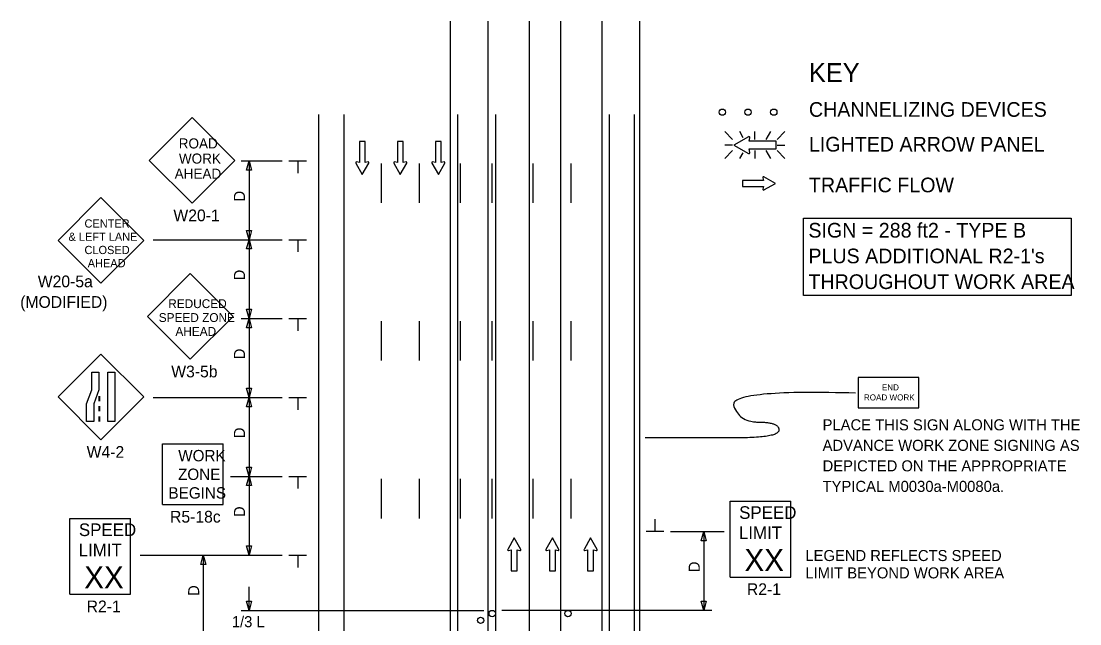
# Model space of a CAD drawing. Extents: x 16730 to 19504, y 5662 to 6979.
# Drawn here: x 16730 to 17400, y 6547 to 6929 of the extents above; entities that cross this region are included whole.
import ezdxf

# ---------------------------------------------------------------- set-up
doc = ezdxf.new("R2010")
doc.units = 0
for name, color, linetype in [('ALI_LEGAL_EX', 7, 'Continuous'), ('MT_SCRATCH_LEVEL_E', 7, 'Continuous'), ('PAVT_EDGE_EX', 7, 'Continuous'), ('TRAFFIC_SIGNS_PR', 7, 'Continuous'), ('TYPICAL_TEXT_DIMEN_EX', 7, 'Continuous'), ('TYPICAL_TEXT_DIMEN_PR', 7, 'Continuous')]:
    doc.layers.add(name, color=color, linetype=linetype)

msp = doc.modelspace()

# ---------------------------------------------------------------- linework, layer by layer
at = {"layer": 'ALI_LEGAL_EX'}
for p, q in [((17001.36, 6131.68), (17001.36, 6928.96)), ((17001.36, 6131.68), (17001.36, 6928.96)), ((17025.36, 6131.68), (17025.36, 6928.96)), ((17025.36, 6131.68), (17025.36, 6928.96)), ((17051.36, 6131.68), (17051.36, 6928.96)), ((17051.36, 6131.68), (17051.36, 6928.96)), ((17071.36, 6131.68), (17071.36, 6928.96)), ((17071.36, 6131.68), (17071.36, 6928.96)), ((17097.36, 6131.68), (17097.36, 6928.96)), ((17097.36, 6131.68), (17097.36, 6928.96)), ((17121.36, 6131.68), (17121.36, 6928.96)), ((17121.36, 6131.68), (17121.36, 6928.96))]:
    msp.add_line(p, q, dxfattribs=at)
for points in [[(16957.81, 6813.81), (16957.81, 6838.81)], [(16981.81, 6813.81), (16981.81, 6838.81)], [(17007.81, 6813.81), (17007.81, 6838.81)], [(17027.81, 6813.81), (17027.81, 6838.81)], [(17053.81, 6813.81), (17053.81, 6838.81)], [(17077.81, 6813.81), (17077.81, 6838.81)], [(16957.81, 6713.81), (16957.81, 6738.81)], [(16981.81, 6713.81), (16981.81, 6738.81)], [(17007.81, 6713.81), (17007.81, 6738.81)], [(17027.81, 6713.81), (17027.81, 6738.81)], [(17053.81, 6713.81), (17053.81, 6738.81)], [(17077.81, 6713.81), (17077.81, 6738.81)], [(16957.81, 6613.81), (16957.81, 6638.81)], [(16981.81, 6613.81), (16981.81, 6638.81)], [(17007.81, 6613.81), (17007.81, 6638.81)], [(17027.81, 6613.81), (17027.81, 6638.81)], [(17053.81, 6613.81), (17053.81, 6638.81)], [(17077.81, 6613.81), (17077.81, 6638.81)]]:
    msp.add_lwpolyline(points, dxfattribs=at)
at = {"layer": 'MT_SCRATCH_LEVEL_E'}
for p, q in [((16947.41, 6852.65), (16943.67, 6852.65)), ((16943.67, 6852.65), (16943.67, 6839.4)), ((16947.41, 6852.65), (16943.67, 6852.65)), ((16943.67, 6852.65), (16943.67, 6839.4)), ((16947.41, 6839.4), (16947.41, 6852.65)), ((16947.41, 6839.4), (16947.41, 6852.65)), ((16971.48, 6852.65), (16967.74, 6852.65)), ((16967.74, 6852.65), (16967.74, 6839.4)), ((16971.48, 6852.65), (16967.74, 6852.65)), ((16967.74, 6852.65), (16967.74, 6839.4)), ((16971.48, 6839.4), (16971.48, 6852.65)), ((16971.48, 6839.4), (16971.48, 6852.65)), ((16995.55, 6852.65), (16991.81, 6852.65)), ((16991.81, 6852.65), (16991.81, 6839.4)), ((16995.55, 6852.65), (16991.81, 6852.65)), ((16991.81, 6852.65), (16991.81, 6839.4)), ((16995.55, 6839.4), (16995.55, 6852.65)), ((16995.55, 6839.4), (16995.55, 6852.65)), ((16941.41, 6839.03), (16945.56, 6831.79)), ((16941.41, 6839.03), (16945.56, 6831.79)), ((16943.67, 6839.4), (16941.89, 6839.71)), ((16943.67, 6839.4), (16941.89, 6839.71)), ((16945.56, 6831.79), (16949.67, 6839.03)), ((16945.56, 6831.79), (16949.67, 6839.03)), ((16949.19, 6839.71), (16947.41, 6839.4)), ((16949.19, 6839.71), (16947.41, 6839.4)), ((16965.48, 6839.03), (16969.63, 6831.79)), ((16965.48, 6839.03), (16969.63, 6831.79)), ((16967.74, 6839.4), (16965.96, 6839.71)), ((16967.74, 6839.4), (16965.96, 6839.71)), ((16969.63, 6831.79), (16973.74, 6839.03)), ((16969.63, 6831.79), (16973.74, 6839.03)), ((16973.26, 6839.71), (16971.48, 6839.4)), ((16973.26, 6839.71), (16971.48, 6839.4)), ((16989.55, 6839.03), (16993.7, 6831.79)), ((16989.55, 6839.03), (16993.7, 6831.79)), ((16991.81, 6839.4), (16990.03, 6839.71)), ((16991.81, 6839.4), (16990.03, 6839.71)), ((16993.7, 6831.79), (16997.81, 6839.03)), ((16993.7, 6831.79), (16997.81, 6839.03)), ((16997.33, 6839.71), (16995.55, 6839.4)), ((16997.33, 6839.71), (16995.55, 6839.4)), ((17199.58, 6827.97), (17186.32, 6827.97)), ((17186.32, 6827.97), (17186.32, 6824.23)), ((17199.58, 6827.97), (17186.32, 6827.97)), ((17186.32, 6827.97), (17186.32, 6824.23)), ((17199.26, 6829.75), (17199.58, 6827.97)), ((17199.26, 6829.75), (17199.58, 6827.97)), ((17207.19, 6826.12), (17199.94, 6830.23)), ((17207.19, 6826.12), (17199.94, 6830.23)), ((17199.94, 6821.98), (17207.19, 6826.12)), ((17199.94, 6821.98), (17207.19, 6826.12)), ((17186.32, 6824.23), (17199.58, 6824.23)), ((17186.32, 6824.23), (17199.58, 6824.23)), ((17199.58, 6824.23), (17199.26, 6822.45)), ((17199.58, 6824.23), (17199.26, 6822.45)), ((17041.75, 6601.44), (17037.64, 6594.2)), ((17041.75, 6601.44), (17037.64, 6594.2)), ((17045.89, 6594.2), (17041.75, 6601.44)), ((17045.89, 6594.2), (17041.75, 6601.44)), ((17065.92, 6601.44), (17061.81, 6594.2)), ((17065.92, 6601.44), (17061.81, 6594.2)), ((17070.06, 6594.2), (17065.92, 6601.44)), ((17070.06, 6594.2), (17065.92, 6601.44)), ((17090.09, 6601.44), (17085.97, 6594.2)), ((17090.09, 6601.44), (17085.97, 6594.2)), ((17094.23, 6594.2), (17090.09, 6601.44)), ((17094.23, 6594.2), (17090.09, 6601.44)), ((17038.12, 6593.52), (17039.89, 6593.83)), ((17038.12, 6593.52), (17039.89, 6593.83)), ((17039.89, 6593.83), (17039.89, 6580.58)), ((17039.89, 6593.83), (17039.89, 6580.58)), ((17043.64, 6580.58), (17043.64, 6593.83)), ((17043.64, 6593.83), (17045.41, 6593.52)), ((17043.64, 6580.58), (17043.64, 6593.83)), ((17043.64, 6593.83), (17045.41, 6593.52)), ((17062.29, 6593.52), (17064.06, 6593.83)), ((17062.29, 6593.52), (17064.06, 6593.83)), ((17064.06, 6593.83), (17064.06, 6580.58)), ((17064.06, 6593.83), (17064.06, 6580.58)), ((17067.81, 6580.58), (17067.81, 6593.83)), ((17067.81, 6593.83), (17069.58, 6593.52)), ((17067.81, 6580.58), (17067.81, 6593.83)), ((17067.81, 6593.83), (17069.58, 6593.52)), ((17086.46, 6593.52), (17088.23, 6593.83)), ((17086.46, 6593.52), (17088.23, 6593.83)), ((17088.23, 6593.83), (17088.23, 6580.58)), ((17088.23, 6593.83), (17088.23, 6580.58)), ((17091.98, 6580.58), (17091.98, 6593.83)), ((17091.98, 6593.83), (17093.75, 6593.52)), ((17091.98, 6580.58), (17091.98, 6593.83)), ((17091.98, 6593.83), (17093.75, 6593.52)), ((17039.89, 6580.58), (17043.64, 6580.58)), ((17039.89, 6580.58), (17043.64, 6580.58)), ((17064.06, 6580.58), (17067.81, 6580.58)), ((17064.06, 6580.58), (17067.81, 6580.58)), ((17088.23, 6580.58), (17091.98, 6580.58)), ((17088.23, 6580.58), (17091.98, 6580.58))]:
    msp.add_line(p, q, dxfattribs=at)
for centre, start, end in [((16941.82, 6839.25), 80.03619, 209.77312), ((16941.82, 6839.25), 80.03619, 209.77312), ((16949.26, 6839.25), 330.42484, 99.96381), ((16949.26, 6839.25), 330.42484, 99.96381), ((16965.89, 6839.25), 80.03619, 209.77312), ((16965.89, 6839.25), 80.03619, 209.77312), ((16973.33, 6839.25), 330.42484, 99.96381), ((16973.33, 6839.25), 330.42484, 99.96381), ((16989.96, 6839.25), 80.03619, 209.77312), ((16989.96, 6839.25), 80.03619, 209.77312), ((16997.4, 6839.25), 330.42484, 99.96381), ((16997.4, 6839.25), 330.42484, 99.96381), ((17199.72, 6829.82), 60.42484, 189.96381), ((17199.72, 6829.82), 60.42484, 189.96381), ((17199.72, 6822.38), 170.03619, 299.77312), ((17199.72, 6822.38), 170.03619, 299.77312), ((17038.04, 6593.98), 150.42484, 279.96381), ((17038.04, 6593.98), 150.42484, 279.96381), ((17045.48, 6593.98), 260.03619, 29.77312), ((17045.48, 6593.98), 260.03619, 29.77312), ((17062.21, 6593.98), 150.42484, 279.96381), ((17062.21, 6593.98), 150.42484, 279.96381), ((17069.65, 6593.98), 260.03619, 29.77312), ((17069.65, 6593.98), 260.03619, 29.77312), ((17086.38, 6593.98), 150.42484, 279.96381), ((17086.38, 6593.98), 150.42484, 279.96381), ((17093.82, 6593.98), 260.03619, 29.77312), ((17093.82, 6593.98), 260.03619, 29.77312)]:
    msp.add_arc(centre, 0.463, start, end, dxfattribs=at)
at = {"layer": 'PAVT_EDGE_EX'}
for p, q in [((16917.81, 6869.88), (16917.81, 6101.02)), ((16933.81, 6869.88), (16933.81, 6101.02)), ((17005.81, 6869.88), (17005.81, 6101.02)), ((17029.81, 6869.88), (17029.81, 6101.02)), ((17101.81, 6869.88), (17101.81, 6101.02)), ((17117.81, 6869.88), (17117.81, 6101.02))]:
    msp.add_line(p, q, dxfattribs=at)
at = {"layer": 'TRAFFIC_SIGNS_PR'}
for p, q in [((16837.75, 6867.89), (16810.59, 6840.74)), ((16864.9, 6840.74), (16837.75, 6867.89)), ((17175.05, 6858.93), (17179.98, 6853.99)), ((17186.81, 6855.11), (17184.6, 6858.93)), ((17194.13, 6853.99), (17194.13, 6858.93)), ((17201.37, 6853.99), (17204.22, 6858.93)), ((17208.28, 6853.99), (17213.22, 6858.93)), ((17179.98, 6850.44), (17175.05, 6850.44)), ((17175.05, 6841.95), (17179.98, 6846.88)), ((17184.56, 6841.95), (17186.67, 6845.61)), ((17194.13, 6846.88), (17194.13, 6841.95)), ((17204.26, 6841.95), (17201.41, 6846.88)), ((17208.28, 6850.44), (17213.22, 6850.44)), ((17208.28, 6846.88), (17213.22, 6841.95)), ((16810.59, 6840.74), (16837.75, 6813.59)), ((16837.75, 6813.59), (16864.9, 6840.74)), ((16780.03, 6817.18), (16752.88, 6790.03)), ((16807.18, 6790.03), (16780.03, 6817.18)), ((16752.88, 6790.03), (16780.03, 6762.88)), ((16780.03, 6762.88), (16807.18, 6790.03)), ((16836.59, 6768.95), (16809.44, 6741.8)), ((16863.75, 6741.8), (16836.59, 6768.95)), ((16809.44, 6741.8), (16836.59, 6714.65)), ((16836.59, 6714.65), (16863.75, 6741.8)), ((16780.03, 6717.95), (16752.88, 6690.8)), ((16780.03, 6717.95), (16752.88, 6690.8)), ((16807.19, 6690.8), (16780.03, 6717.95)), ((16807.18, 6690.8), (16780.03, 6717.95)), ((16778.78, 6691.29), (16778.78, 6688.09)), ((16779.18, 6691.29), (16779.18, 6688.09)), ((16752.88, 6690.8), (16780.03, 6663.65)), ((16752.88, 6690.8), (16780.03, 6663.65)), ((16778.78, 6684.89), (16778.78, 6681.69)), ((16779.18, 6684.89), (16779.18, 6681.69)), ((16780.03, 6663.65), (16807.19, 6690.8)), ((16780.03, 6663.65), (16807.18, 6690.8)), ((16778.78, 6678.49), (16778.78, 6675.29)), ((16779.18, 6678.49), (16779.18, 6675.29)), ((16818.98, 6622.61), (16818.98, 6661.01)), ((16818.98, 6661.01), (16857.38, 6661.01)), ((16857.38, 6622.61), (16857.38, 6661.01)), ((17178.45, 6624.66), (17216.85, 6624.66)), ((17178.45, 6576.66), (17178.45, 6624.66)), ((17216.85, 6576.66), (17216.85, 6624.66)), ((16818.98, 6622.61), (16857.38, 6622.61)), ((16760.3, 6613.76), (16798.7, 6613.76)), ((16760.3, 6565.76), (16760.3, 6613.76)), ((16798.7, 6565.76), (16798.7, 6613.76)), ((17178.45, 6576.66), (17216.85, 6576.66)), ((16760.3, 6565.76), (16798.7, 6565.76))]:
    msp.add_line(p, q, dxfattribs=at)
for points in [[(17190.06, 6855.72), (17180.77, 6850.44), (17190.06, 6845.12)], [(17190.94, 6845.75), (17190.53, 6848.01), (17207.55, 6848.01), (17207.55, 6852.82), (17190.53, 6852.82), (17190.94, 6855.1)]]:
    msp.add_lwpolyline(points, dxfattribs=at)
for points in [[(16778.78, 6706.54), (16778.78, 6695.36), (16775.44, 6686.47), (16775.44, 6675.29), (16770.95, 6675.29), (16770.95, 6686.47), (16774.29, 6695.36), (16774.29, 6706.54)], [(16778.78, 6706.54), (16778.78, 6695.36), (16775.44, 6686.47), (16775.44, 6675.29), (16770.95, 6675.29), (16770.95, 6686.47), (16774.29, 6695.36), (16774.29, 6706.54)], [(16788.92, 6706.54), (16788.92, 6675.29), (16784.43, 6675.29), (16784.43, 6706.54)], [(16788.92, 6706.54), (16788.92, 6675.29), (16784.43, 6675.29), (16784.43, 6706.54)], [(17259.6, 6683.82), (17298, 6683.82), (17298, 6703.02), (17259.6, 6703.02)]]:
    msp.add_lwpolyline(points, close=True, dxfattribs=at)
for centre in [(17173.56, 6871.28), (17189.86, 6871.28), (17206.16, 6871.28), (17020.5, 6549.17), (17027.8, 6553.52), (17075.79, 6553.52), (17075.79, 6553.52)]:
    msp.add_circle(centre, 2, dxfattribs=at)
for centre, radius, start, end in [((17190.35, 6855.19), 0.598, 350.73078, 118.89165), ((17190.35, 6845.64), 0.597, 241.48329, 9.95933)]:
    msp.add_arc(centre, radius, start, end, dxfattribs=at)
at = {"layer": 'TYPICAL_TEXT_DIMEN_EX'}
msp.add_lwpolyline([(17225.06, 6804.2), (17394.51, 6804.2), (17394.51, 6755.01), (17225.06, 6755.01)], close=True, dxfattribs=at)
at = {"layer": 'TYPICAL_TEXT_DIMEN_PR'}
for p, q in [((16868.81, 6840.47), (16894.81, 6840.47)), ((16872.24, 6834.6), (16873.81, 6840.47)), ((16873.81, 6840.47), (16875.38, 6834.6)), ((16873.81, 6840.47), (16873.81, 6790.47)), ((16899.06, 6840.47), (16910.31, 6840.47)), ((16904.69, 6840.47), (16904.69, 6832.68)), ((16873.81, 6834.6), (16872.24, 6834.6)), ((16875.38, 6834.6), (16873.81, 6834.6)), ((16873.81, 6790.47), (16872.24, 6796.33)), ((16872.24, 6796.33), (16873.81, 6796.33)), ((16873.81, 6796.33), (16875.38, 6796.33)), ((16875.38, 6796.33), (16873.81, 6790.47)), ((16813.08, 6790.47), (16894.81, 6790.47)), ((16868.81, 6790.47), (16894.81, 6790.47)), ((16872.24, 6784.6), (16873.81, 6790.47)), ((16873.81, 6790.47), (16873.81, 6740.47)), ((16873.81, 6790.47), (16875.38, 6784.6)), ((16899.06, 6790.47), (16910.31, 6790.47)), ((16904.69, 6790.47), (16904.69, 6782.68)), ((16873.81, 6784.6), (16872.24, 6784.6)), ((16875.38, 6784.6), (16873.81, 6784.6)), ((16873.81, 6740.47), (16872.24, 6746.33)), ((16872.24, 6746.33), (16873.81, 6746.33)), ((16873.81, 6746.33), (16875.38, 6746.33)), ((16875.38, 6746.33), (16873.81, 6740.47)), ((16868.81, 6740.47), (16894.81, 6740.47)), ((16872.24, 6734.6), (16873.81, 6740.47)), ((16873.81, 6740.47), (16873.81, 6690.47)), ((16873.81, 6740.47), (16875.38, 6734.6)), ((16899.06, 6740.47), (16910.31, 6740.47)), ((16904.69, 6740.47), (16904.69, 6732.68)), ((16873.81, 6734.6), (16872.24, 6734.6)), ((16875.38, 6734.6), (16873.81, 6734.6)), ((16873.81, 6690.47), (16872.24, 6696.33)), ((16872.24, 6696.33), (16873.81, 6696.33)), ((16873.81, 6696.33), (16875.38, 6696.33)), ((16875.38, 6696.33), (16873.81, 6690.47)), ((16813.08, 6690.47), (16894.81, 6690.47)), ((16868.81, 6690.47), (16894.81, 6690.47)), ((16872.24, 6684.6), (16873.81, 6690.47)), ((16873.81, 6684.6), (16872.24, 6684.6)), ((16873.81, 6690.47), (16875.38, 6684.6)), ((16873.81, 6690.47), (16873.81, 6640.47)), ((16875.38, 6684.6), (16873.81, 6684.6)), ((16899.06, 6690.47), (16910.31, 6690.47)), ((16904.69, 6690.47), (16904.69, 6682.68)), ((16873.81, 6640.47), (16872.24, 6646.33)), ((16872.24, 6646.33), (16873.81, 6646.33)), ((16873.81, 6646.33), (16875.38, 6646.33)), ((16875.38, 6646.33), (16873.81, 6640.47)), ((16862.15, 6640.47), (16894.81, 6640.47)), ((16872.24, 6634.6), (16873.81, 6640.47)), ((16873.81, 6640.47), (16873.81, 6590.47)), ((16873.81, 6640.47), (16875.38, 6634.6)), ((16899.06, 6640.47), (16910.31, 6640.47)), ((16904.69, 6640.47), (16904.69, 6632.68)), ((16873.81, 6634.6), (16872.24, 6634.6)), ((16875.38, 6634.6), (16873.81, 6634.6)), ((17130.94, 6605.53), (17130.94, 6613.32)), ((17136.56, 6605.53), (17125.31, 6605.53)), ((17140.81, 6605.53), (17174.82, 6605.53)), ((17160.24, 6599.67), (17161.81, 6605.53)), ((17161.81, 6605.53), (17161.81, 6555.53)), ((17161.81, 6605.53), (17163.38, 6599.67)), ((17161.81, 6599.67), (17160.24, 6599.67)), ((17163.38, 6599.67), (17161.81, 6599.67)), ((16873.81, 6590.47), (16872.24, 6596.33)), ((16872.24, 6596.33), (16873.81, 6596.33)), ((16873.81, 6596.33), (16875.38, 6596.33)), ((16875.38, 6596.33), (16873.81, 6590.47)), ((16804.9, 6590.47), (16894.81, 6590.47)), ((16843.25, 6584.6), (16844.82, 6590.47)), ((16844.82, 6584.6), (16843.25, 6584.6)), ((16844.82, 6590.47), (16844.82, 6540.47)), ((16844.82, 6590.47), (16846.39, 6584.6)), ((16846.39, 6584.6), (16844.82, 6584.6)), ((16899.06, 6590.47), (16910.31, 6590.47)), ((16904.69, 6590.47), (16904.69, 6582.68)), ((16873.81, 6555.53), (16873.81, 6570.46)), ((16873.81, 6555.53), (16872.24, 6561.4)), ((16872.24, 6561.4), (16873.81, 6561.4)), ((16873.81, 6561.4), (16875.38, 6561.4)), ((16875.38, 6561.4), (16873.81, 6555.53)), ((17161.81, 6555.53), (17160.24, 6561.4)), ((17160.24, 6561.4), (17161.81, 6561.4)), ((17161.81, 6561.4), (17163.38, 6561.4)), ((17163.38, 6561.4), (17161.81, 6555.53)), ((16868.81, 6555.53), (17022.42, 6555.53)), ((17166.81, 6555.53), (17034.02, 6555.53))]:
    msp.add_line(p, q, dxfattribs=at)
msp.add_open_spline([(17257.86, 6693.27), (17177.21, 6695.43), (17184.21, 6674.84), (17209.39, 6674.84), (17209.39, 6664.93), (17159.74, 6664.93), (17124.68, 6664.93)], degree=2, dxfattribs=at)

# ---------------------------------------------------------------- texts
at = {"layer": 'TRAFFIC_SIGNS_PR'}
for s, height, p in [('ROAD', 6.4, (16829.29, 6848.27)), ('WORK', 6.4, (16829.4, 6838.67)), ('AHEAD', 6.4, (16826.71, 6829.07)), ('W20-1', 7.44, (16825.91, 6802.15)), ('CENTER', 5.2, (16769.61, 6798.14)), ('& LEFT LANE', 5.2, (16759.48, 6789.74)), ('CLOSED', 5.2, (16769.61, 6781.34)), ('AHEAD', 5.2, (16771.64, 6772.94)), ('W20-5a', 7.44, (16740.03, 6760.3)), ('(MODIFIED)', 7.44, (16728.89, 6747.26)), ('REDUCED', 5.6, (16822.65, 6747.11)), ('SPEED ZONE', 5.6, (16816.64, 6738.31)), ('AHEAD', 5.6, (16827.2, 6729.51)), ('W3-5b', 7.44, (16824.55, 6703.21)), ('END', 3.831, (17274.6, 6694.95)), ('ROAD WORK', 3.831, (17263.21, 6688.57)), ('PLACE THIS SIGN ALONG WITH THE', 7, (17237.06, 6669.63)), ('W4-2', 7.44, (16770.99, 6652.21)), ('W4-2', 7.44, (16770.99, 6652.21)), ('ADVANCE WORK ZONE SIGNING AS', 7, (17237.06, 6656.63)), ('WORK', 7.217, (16828.98, 6649.98)), ('ZONE', 7.217, (16828.86, 6638.17)), ('DEPICTED ON THE APPROPRIATE', 7, (17237.06, 6643.63)), ('TYPICAL M0030a-M0080a.', 7, (17237.06, 6630.62)), ('BEGINS', 7.217, (16822.79, 6626.36)), ('R5-18c', 7.44, (16823.79, 6611.17)), ('SPEED', 8, (17184.21, 6613.52)), ('SPEED', 8, (16766.07, 6602.62)), ('LIMIT', 8, (17184.05, 6600.72)), ('LIMIT', 8, (16765.91, 6589.82)), ('XX', 14.031, (17187.56, 6580.41)), ('XX', 14.031, (16769.42, 6569.51)), ('R2-1', 7.44, (17189.12, 6565.22)), ('R2-1', 7.44, (16770.98, 6554.32))]:
    msp.add_text(s, height=height, dxfattribs=at).set_placement(p)
at = {"layer": 'TYPICAL_TEXT_DIMEN_EX'}
for s, height, p in [('KEY', 12, (17228.4, 6890.39)), ('CHANNELIZING DEVICES', 9.3, (17228.4, 6868.34)), ('LIGHTED ARROW PANEL', 9.3, (17228.4, 6846.29)), ('TRAFFIC FLOW', 9.3, (17228.4, 6820.49)), ('SIGN = 288 ft2 - TYPE B', 9.3, (17228.07, 6791.8)), ("PLUS ADDITIONAL R2-1's", 9.3, (17228.07, 6775.5)), ('THROUGHOUT WORK AREA', 9.3, (17228.07, 6759.2))]:
    msp.add_text(s, height=height, dxfattribs=at).set_placement(p)
at = {"layer": 'TYPICAL_TEXT_DIMEN_PR'}
for p in [(16871.25, 6814.68), (16871.25, 6764.68), (16871.25, 6714.68), (16871.25, 6664.68), (16871.25, 6614.68), (17159.25, 6579.75), (16842.26, 6564.68)]:
    msp.add_text('D', height=7, rotation=90, dxfattribs=at).set_placement(p)
for s, p in [('LEGEND REFLECTS SPEED', (17226.16, 6586.79)), ('LIMIT BEYOND WORK AREA', (17226.16, 6575.79)), ('1/3 L', (16862.91, 6544.87))]:
    msp.add_text(s, height=7, dxfattribs=at).set_placement(p)

doc.saveas('drawing.dxf')
